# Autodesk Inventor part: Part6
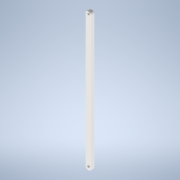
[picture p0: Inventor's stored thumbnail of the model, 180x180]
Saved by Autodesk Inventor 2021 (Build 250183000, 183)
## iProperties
Created: 2021-01
Part Number: Part6
Material: Generic
Document SubType Name: Modeling
Designer: Owner
Density: 1 g/cm^3
Appearance: Default
Mass: 1.79485 g
Surface Area: 19.971 cm^2
Volume: 1.79485 cm^3
Author: Owner
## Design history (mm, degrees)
sketch "Sketch1"
  geometry: L1 (-1.807, 7.49)-(-1.807, -112.51); L2 (3.193, 7.49)-(3.193, -112.51); L3 (3.193, 7.49)-(-1.807, 7.49); A1 r 2.5 centre (0.693, -112.51) between (-1.807, -112.51) and (3.193, -112.51); 1 further point
  constraints: 6 end point, 2 point on circle, 2 tangent, 2 vertical, 1 centre point, 1 horizontal
  dimensions: "d3" = 120 distance of L1.start L1.end
extrude "Extrusion1" new body sketch "Sketch1" distance "d4" = 3; taper "d5" = 0 deg
sketch "Sketch2"
  geometry: 2 further points
hole "Hole1" sketch "Sketch2" at (-0.77, 5.981) diameter "d6" = 2.5; stored, may be unused: countersink angle "d10" = 90 deg, drill point angle "d12" = 118 deg; dims "d7" = 6, "d8" = 4, "d9" = 2, "d11" = 8
sketch "Sketch3"
  geometry: 2 further points
hole "Hole2" sketch "Sketch3" at (-0.623, -111.627) diameter "d13" = 2.5; stored, may be unused: countersink angle "d17" = 90 deg, drill point angle "d19" = 118 deg; dims "d14" = 6, "d15" = 4, "d16" = 2, "d18" = 8
fillet "Fillet1" dims "d20" = 2
body "Solid1"
